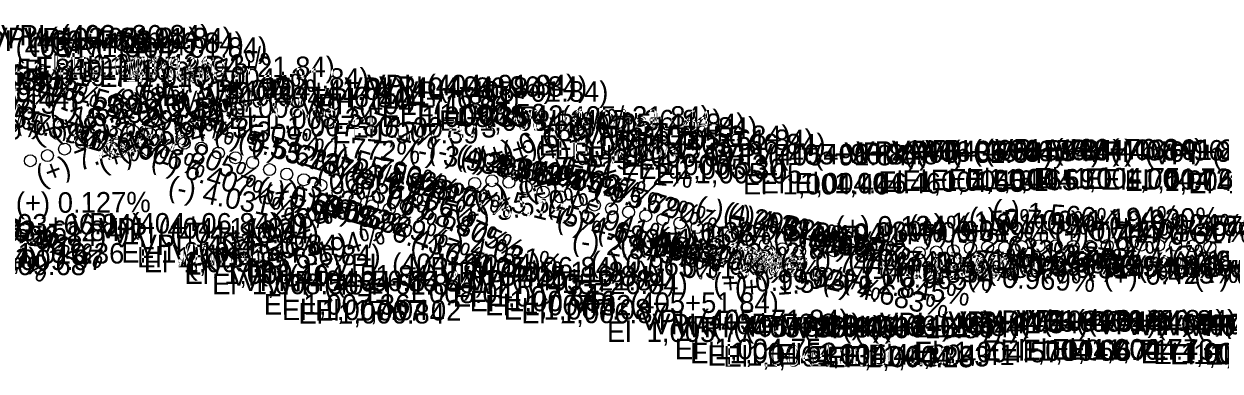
# Model space of a CAD drawing. Extents: x 16970812 to 16976737, y 12558429 to 12559451.
# Drawn here: x 16974747.9 to 16975097.7, y 12558926.1 to 12559027.7 of the extents above; entities that cross this region are included whole.
import ezdxf

# ---------------------------------------------------------------- set-up
doc = ezdxf.new("R2010")
doc.units = 0
doc.layers.add('RD_DDB_GradeTX', color=7, linetype='Continuous')
doc.layers.add('RD_DDB_PI', color=7, linetype='Continuous')

msp = doc.modelspace()

# ---------------------------------------------------------------- linework, layer by layer
at = {"layer": 'RD_DDB_PI'}
for centre in [(16974769.74, 12558994.82), (16974774.74, 12558995.62), (16974779.74, 12558996.42), (16974784.74, 12558995.59), (16974759.74, 12558991.1), (16974764.74, 12558993.02), (16974789.74, 12558994.21), (16974794.74, 12558992.81), (16974799.74, 12558991.37), (16974749.74, 12558987.7), (16974754.74, 12558989.18), (16974804.74, 12558989.95), (16974809.74, 12558988.55), (16974814.74, 12558987.17), (16974819.74, 12558985.09), (16974824.74, 12558983.76), (16974829.74, 12558982.11), (16974879.74, 12558981.07), (16974884.74, 12558981.84), (16974889.74, 12558981.39), (16974834.74, 12558980.5), (16974839.74, 12558978.34), (16974869.74, 12558977.97), (16974874.74, 12558979.51), (16974894.74, 12558979.95), (16974899.74, 12558978.51), (16974904.74, 12558977.12), (16974844.74, 12558976.13), (16974849.74, 12558974.53), (16974859.74, 12558974.41), (16974864.74, 12558976.27), (16974909.74, 12558975.92), (16974914.74, 12558974.71), (16974919.74, 12558973.64), (16974854.74, 12558973.53), (16974924.74, 12558972.66), (16974929.74, 12558971.58), (16974934.74, 12558970.51), (16974939.74, 12558969.43), (16974944.74, 12558968.14), (16974949.74, 12558966.98), (16974954.74, 12558965.82), (16974959.74, 12558964.56), (16974964.74, 12558963.08), (16975069.74, 12558963.07), (16974969.74, 12558961.91), (16974974.74, 12558961.19), (16974979.74, 12558960.95), (16974984.74, 12558961.32), (16974989.74, 12558961.61), (16974994.74, 12558961.53), (16974999.74, 12558961.63), (16975004.74, 12558960.97), (16975009.74, 12558960.73), (16975014.74, 12558960.98), (16975019.74, 12558961.36), (16975024.74, 12558962.07), (16975029.74, 12558962.37), (16975034.74, 12558962.19), (16975039.74, 12558962.54), (16975044.74, 12558962.77), (16975049.74, 12558962.8), (16975054.74, 12558962.62), (16975059.74, 12558962.64), (16975064.74, 12558962.85), (16975074.74, 12558963), (16975079.74, 12558962.95), (16975084.74, 12558962.92), (16975089.74, 12558962.74), (16975094.74, 12558962.35)]:
    msp.add_circle(centre, 1.75, dxfattribs=at)

# ---------------------------------------------------------------- texts
at = {"layer": 'RD_DDB_GradeTX'}
for s, rotation, p in [('(+) 7.173%', 19.7305, (16974783.44, 12559002.92)), ('(-) 5.532%', 344.5396, (16974726.19, 12559014.9)), ('(-) 5.613%', 344.3231, (16974733.31, 12559013.16)), ('(-) 3.309%', 350.6045, (16974719.65, 12559009.41)), ('(+) 7.308%', 20.0734, (16974751.55, 12558992.47)), ('(-) 5.522%', 344.5648, (16974751.23, 12559007.81)), ('(+) 6.308%', 17.5064, (16974756.79, 12558993.48)), ('(-) 8.647%', 336.6189, (16974780.84, 12559007.07)), ('(+) 3.220%', 9.1473, (16974787.26, 12559000.68)), ('(+) 3.199%', 9.0882, (16974794.6, 12559001.84)), ('(-) 8.306%', 337.4469, (16974755.17, 12559002.16)), ('(-) 5.329%', 345.0802, (16974761.22, 12559003.79)), ('(+) 4.640%', 13.0615, (16974762.91, 12558993.83)), ('(-) 6.437%', 342.1594, (16974773.06, 12559003.5)), ('(+) 7.654%', 20.9421, (16974776.09, 12558987.72)), ('(+) 7.705%', 21.07, (16974781.14, 12558989.7)), ('(-) 5.737%', 343.9957, (16974733.98, 12559000.87)), ('(-) 5.690%', 344.1187, (16974738.91, 12558999.32)), ('(-) 5.762%', 343.9296, (16974832.2, 12559001.09)), ('(+) 6.194%', 17.2079, (16974888.92, 12558987.04)), ('(+) 3.199%', 9.0882, (16974715.67, 12558989.21)), ('(-) 5.615%', 344.3167, (16974745.24, 12558997.31)), ('(+) 5.954%', 16.5775, (16974770.52, 12558984.49)), ('(-) 3.309%', 350.6045, (16974798.51, 12558996.36)), ('(+) 6.788%', 18.7474, (16974882.16, 12558985.35)), ('(+) 7.491%', 20.5323, (16974752.73, 12558980.26)), ('(-) 6.606%', 341.7206, (16974764.58, 12558994.15)), ('(-) 8.805%', 336.2393, (16974780.6, 12558994.54)), ('(-) 5.532%', 344.5396, (16974803.11, 12558993.63)), ('(-) 5.613%', 344.3231, (16974810.15, 12558991.6)), ('(+) 3.068%', 8.7226, (16974897.89, 12558986.89)), ('(-) 5.737%', 343.9957, (16974814, 12558990.41)), ('(-) 1.772%', 354.938, (16974826.26, 12558990.03)), ('(-) 5.790%', 343.854, (16974834.12, 12558988.13)), ('(-) 3.938%', 348.8596, (16974860.1, 12558988.45)), ('(-) 4.299%', 347.8682, (16974865.96, 12558988.36)), ('(+) 6.223%', 17.2824, (16974894.93, 12558976.37)), ('(-) 6.407%', 342.2362, (16974784.64, 12558985.94)), ('(-) 5.536%', 344.5286, (16974838.33, 12558986.17)), ('(-) 4.311%', 347.8348, (16974873.91, 12558986.69)), ('(-) 4.323%', 347.8021, (16974875.17, 12558986.45)), ('(+) 7.422%', 20.3594, (16974880.63, 12558972.56)), ('(-) 4.627%', 346.9751, (16974886.4, 12558984.71)), ('(-) 4.659%', 346.8864, (16974891.37, 12558983.66)), ('(+) 3.068%', 8.7226, (16974818.87, 12558974.77)), ('(-) 8.306%', 337.4469, (16974833.27, 12558982.72)), ('(-) 4.823%', 346.442, (16974843.06, 12558982.74)), ('(-) 6.606%', 341.7206, (16974844.06, 12558980.54)), ('(-) 4.810%', 346.4763, (16974850.19, 12558980.98)), ('(-) 5.027%', 345.8922, (16974896.4, 12558983.57)), ('(-) 1.772%', 354.938, (16974905.93, 12558982.97)), ('(-) 4.031%', 348.6043, (16974789.71, 12558977.45)), ('(-) 5.690%', 344.1187, (16974815.66, 12558977.49)), ('(-) 4.277%', 347.9279, (16974853.78, 12558978.55)), ('(-) 5.762%', 343.9296, (16974908.88, 12558979)), ('(-) 5.790%', 343.854, (16974914.11, 12558977.47)), ('(+) 6.223%', 17.2824, (16974815.21, 12558964.13)), ('(-) 5.615%', 344.3167, (16974822.08, 12558975.74)), ('(-) 5.522%', 344.5648, (16974824.97, 12558975.01)), ('(-) 8.647%', 336.6189, (16974853.86, 12558975.5)), ('(+) 3.550%', 10.0648, (16974874.49, 12558967.89)), ('(-) 5.145%', 345.5743, (16974880.06, 12558975.48)), ('(-) 11.243%', 330.6573, (16974716.68, 12558972.27)), ('(-) 7.074%', 340.5204, (16974725.32, 12558971.44)), ('(+) 0.127%', 0.3642, (16974745.51, 12558972.36)), ('(+) 6.788%', 18.7474, (16974806.67, 12558959.73)), ('(-) 5.329%', 345.0802, (16974835.27, 12558971.64)), ('(-) 8.805%', 336.2393, (16974858.23, 12558973.48)), ('(-) 5.941%', 343.4548, (16974900.61, 12558972.74)), ('(-) 4.299%', 347.8682, (16974944.06, 12558971.58)), ('(-) 4.311%', 347.8348, (16974952, 12558969.85)), ('(-) 4.323%', 347.8021, (16974953.25, 12558969.57)), ('(-) 1.566%', 355.5233, (16975030.94, 12558970.36)), ('(-) 7.041%', 340.6064, (16974731.62, 12558969.24)), ('(-) 6.962%', 340.807, (16974734.83, 12558968.18)), ('(+) 7.422%', 20.3594, (16974801.76, 12558956.1)), ('(-) 6.437%', 342.1594, (16974845.29, 12558967.65)), ('(-) 4.683%', 346.8212, (16974903.37, 12558968.2)), ('(-) 5.145%', 345.5743, (16974960.37, 12558967.22)), ('(+) 1.157%', 3.311, (16975007.01, 12558965.61)), ('(-) 0.115%', 359.6692, (16975021.94, 12558966.28)), ('(-) 0.700%', 357.9941, (16975024.18, 12558968.04)), ('(+) 1.194%', 3.4171, (16975047.06, 12558966.41)), ('(+) 0.930%', 2.6636, (16975058.4, 12558966.41)), ('(+) 0.124%', 0.3549, (16975065.25, 12558965.9)), ('(-) 0.557%', 358.4036, (16975073.91, 12558966.35)), ('(-) 0.303%', 359.1328, (16975088.19, 12558965.8)), ('(+) 6.194%', 17.2079, (16974816.27, 12558951.98)), ('(-) 5.536%', 344.5286, (16974915.25, 12558964.87)), ('(-) 4.823%', 346.442, (16974920.7, 12558964.02)), ('(+) 1.471%', 4.2067, (16974922.41, 12558959.74)), ('(+) 1.157%', 3.311, (16974927.15, 12558960.99)), ('(+) 0.384%', 1.1002, (16974933.51, 12558963.35)), ('(+) 1.194%', 3.4171, (16974967.21, 12558961.64)), ('(-) 4.659%', 346.8864, (16974969.15, 12558965.54)), ('(-) 5.027%', 345.8922, (16974973.84, 12558964.11)), ('(+) 1.417%', 4.0537, (16974977.4, 12558961.13)), ('(+) 0.930%', 2.6636, (16974978.49, 12558962.69)), ('(+) 0.124%', 0.3549, (16974985.26, 12558965.4)), ('(+) 0.904%', 2.589, (16975003.91, 12558963.1)), ('(-) 0.319%', 359.0866, (16975010.26, 12558964.28)), ('(+) 0.477%', 1.3674, (16975049.39, 12558963.12)), ('(-) 0.744%', 357.8701, (16975049.37, 12558964.64)), ('(-) 0.740%', 357.881, (16975069.25, 12558965.08)), ('(+) 0.617%', 1.766, (16975070.74, 12558962.68)), ('(+) 3.550%', 10.0648, (16974795.8, 12558953.92)), ('(-) 6.407%', 342.2362, (16974860.59, 12558961.61)), ('(-) 4.031%', 348.6043, (16974868.03, 12558961.67)), ('(-) 2.845%', 351.9036, (16974907.89, 12558961.61)), ('(-) 4.810%', 346.4763, (16974927.83, 12558962.31)), ('(-) 4.277%', 347.9279, (16974931.9, 12558961.84)), ('(-) 3.938%', 348.8596, (16974936.18, 12558961.23)), ('(-) 2.632%', 352.5034, (16974937.48, 12558960.74)), ('(+) 2.849%', 8.1075, (16974958.97, 12558955.74)), ('(-) 5.941%', 343.4548, (16974980.5, 12558961.52)), ('(-) 2.632%', 352.5034, (16975018.32, 12558962.21)), ('(-) 1.877%', 354.6387, (16975035.42, 12558958.88)), ('(+) 2.849%', 8.1075, (16975039.82, 12558955.13)), ('(-) 0.965%', 357.2376, (16974913.5, 12558955.14)), ('(-) 0.744%', 357.8701, (16974968.98, 12558955.63)), ('(-) 0.740%', 357.881, (16974988.86, 12558956.05)), ('(+) 1.471%', 4.2067, (16975003.06, 12558953.64)), ('(+) 1.543%', 4.4116, (16975035.73, 12558953.57)), ('(-) 0.983%', 357.1871, (16975038.2, 12558955.9)), ('(+) 1.417%', 4.0537, (16975058.04, 12558954.81)), ('(+) 0.832%', 2.3829, (16975078.56, 12558954.42)), ('(-) 1.411%', 355.9634, (16975083.33, 12558956.47)), ('(+) 0.904%', 2.589, (16975084.36, 12558954.73)), ('(-) 0.319%', 359.0866, (16974930.08, 12558953.56)), ('(-) 0.969%', 357.226, (16974943.73, 12558954.91)), ('(-) 4.627%', 346.9751, (16974961.51, 12558955.02)), ('(+) 0.085%', 0.2447, (16974993.66, 12558953.36)), ('(+) 0.832%', 2.3829, (16974998.64, 12558951.09)), ('(-) 0.303%', 359.1328, (16975008.02, 12558955.01)), ('(-) 0.209%', 359.401, (16975013.53, 12558954.64)), ('(+) 0.384%', 1.1002, (16975013.73, 12558952.89)), ('(+) 0.999%', 2.8602, (16975029.52, 12558952.7)), ('(-) 0.314%', 359.1012, (16975045.08, 12558953.57)), ('(-) 0.598%', 358.2878, (16975053.5, 12558954.5)), ('(-) 0.545%', 358.4399, (16975058.4, 12558954.2)), ('(+) 0.425%', 1.2186, (16975063.71, 12558951.09)), ('(+) 0.085%', 0.2447, (16975073.66, 12558953.7)), ('(-) 0.624%', 358.2125, (16975083.49, 12558954.07)), ('(-) 0.209%', 359.401, (16975093.52, 12558953.8)), ('(+) 0.999%', 2.8602, (16974949.62, 12558948.71)), ('(+) 1.543%', 4.4116, (16974955.98, 12558947.42)), ('(-) 4.683%', 346.8212, (16974981.13, 12558950)), ('(-) 2.845%', 351.9036, (16974987.05, 12558950.35)), ('(-) 0.965%', 357.2376, (16974993.4, 12558951.28)), ('(-) 0.969%', 357.226, (16975023.63, 12558951.04)), ('(+) 0.310%', 0.8881, (16975090.24, 12558951.08))]:
    msp.add_text(s, height=6, rotation=rotation, dxfattribs=at).set_placement(p)
at = {"layer": 'RD_DDB_PI'}
for s, p in [('VPI  (403+71.84)', (16974728.04, 12559018.02)), ('VPI  (403+76.84)', (16974731.5, 12559019.82)), ('VPI  (403+81.84)', (16974737.74, 12559020.62)), ('VPI  (403+86.84)', (16974741.21, 12559021.42)), ('VPI  (403+91.84)', (16974747.86, 12559020.59)), ('VPI  (403+96.84)', (16974751.33, 12559019.21)), ('VPI  (404+01.84)', (16974758.16, 12559017.81)), ('VPI  (403+51.84)', (16974707.63, 12559011.54)), ('El  1,011.10', (16974747.89, 12559011.32)), ('El  1,011.26', (16974751.12, 12559012.12)), ('El  1,011.42', (16974756.15, 12559012.92)), ('El  1,011.26', (16974761.12, 12559012.09)), ('VPI  (404+21.84)', (16974777.92, 12559012.17)), ('VPI  (403+41.84)', (16974697.86, 12559008.13)), ('VPI  (403+46.84)', (16974701.33, 12559009.96)), ('El  1,010.74', (16974740, 12559009.52)), ('El  1,010.98', (16974764.73, 12559010.71)), ('El  1,010.70', (16974769.88, 12559009.31)), ('VPI  (404+31.84)', (16974787.86, 12559008.76)), ('VPI  (404+41.84)', (16974798.27, 12559005.5)), ('VPI  (404+86.84)', (16974841.62, 12559006.07)), ('VPI  (404+91.84)', (16974848.27, 12559006.84)), ('VPI  (404+96.84)', (16974851.74, 12559006.39)), ('VPI  (405+01.84)', (16974857.92, 12559004.95)), ('El  1,009.13', (16974714.44, 12559001.46)), ('El  1,009.44', (16974718.28, 12559003.04)), ('El  1,009.57', (16974788.23, 12559003.67)), ('VPI  (404+46.84)', (16974801.74, 12559003.34)), ('VPI  (404+71.84)', (16974828.45, 12559001.27)), ('VPI  (404+76.84)', (16974831.92, 12559002.97)), ('El  1,008.76', (16974708.34, 12558999.63)), ('El  1,008.89', (16974798.05, 12559000.26)), ('El  1,008.24', (16974807.81, 12558997)), ('El  1,008.35', (16974852.55, 12558997.57)), ('El  1,008.50', (16974857.81, 12558998.34)), ('El  1,008.42', (16974862.84, 12558997.89)), ('VPI  (405+31.84)', (16974887.63, 12558997.66)), ('El  1,007.80', (16974813.23, 12558994.84)), ('El  1,007.73', (16974843.26, 12558994.47)), ('El  1,008.13', (16974869.32, 12558996.45)), ('VPI  (405+36.84)', (16974891.09, 12558996.58)), ('VPI  (405+41.84)', (16974898.04, 12558995.51)), ('VPI  (405+46.84)', (16974901.5, 12558994.43)), ('El  1,007.39', (16974838.05, 12558992.77)), ('VPI  (405+56.84)', (16974911.27, 12558991.98)), ('VPI  (405+61.84)', (16974918.04, 12558990.82)), ('El  1,006.67', (16974898.46, 12558989.16)), ('El  1,006.45', (16974903.08, 12558988.08)), ('El  1,006.24', (16974907.93, 12558987.01)), ('VPI  (405+66.84)', (16974921.5, 12558989.56)), ('VPI  (405+96.84)', (16974951.5, 12558986.61)), ('VPI  (406+06.84)', (16974961.62, 12558986.63)), ('VPI  (406+31.84)', (16974987.86, 12558987.07)), ('VPI  (406+36.84)', (16974991.33, 12558987.37)), ('VPI  (406+46.84)', (16975001.74, 12558987.54)), ('VPI  (406+51.84)', (16975008.04, 12558987.77)), ('VPI  (406+56.84)', (16975011.5, 12558987.8)), ('VPI  (406+76.84)', (16975031.92, 12558988.07)), ('VPI  (406+91.84)', (16975048.27, 12558987.92)), ('VPI  (406+96.84)', (16975051.74, 12558987.74)), ('VPI  (407+01.84)', (16975058.33, 12558987.35)), ('VPI  (407+21.84)', (16975078.1, 12558986.68)), ('El  1,006.02', (16974912.84, 12558985.93)), ('El  1,005.53', (16974922.43, 12558983.48)), ('VPI  (405+91.84)', (16974948.04, 12558986.32)), ('El  1,005.30', (16974927.52, 12558982.32)), ('El  1,005.05', (16974932.72, 12558981.06)), ('El  1,004.75', (16975043.26, 12558979.57)), ('El  1,004.40', (16974958.17, 12558977.82)), ('El  1,004.46', (16974963.28, 12558978.11)), ('El  1,004.46', (16974973.28, 12558978.13)), ('El  1,004.55', (16974997.84, 12558978.57)), ('El  1,004.61', (16975004.82, 12558978.87)), ('El  1,004.65', (16975013.08, 12558979.04)), ('El  1,004.69', (16975018.28, 12558979.27)), ('El  1,004.70', (16975023.34, 12558979.3)), ('El  1,004.72', (16975058.14, 12558979.42)), ('El  1,004.69', (16975063.28, 12558979.24)), ('El  1,004.61', (16975069.82, 12558978.85)), ('El  1,004.47', (16975088.46, 12558978.18)), ('VPI  (403+66.84)', (16974721.33, 12558966.1)), ('VPI  (404+06.84)', (16974761.62, 12558966.37)), ('VPI  (403+56.84)', (16974711.09, 12558962.7)), ('VPI  (403+61.84)', (16974717.86, 12558964.18)), ('VPI  (404+11.84)', (16974769.81, 12558964.95)), ('VPI  (404+16.84)', (16974773.27, 12558963.55)), ('VPI  (404+26.84)', (16974781.39, 12558960.09)), ('VPI  (403+36.84)', (16974690.91, 12558956.26)), ('El  1,009.97', (16974728.46, 12558955.68)), ('El  1,010.36', (16974734.41, 12558957.6)), ('El  1,010.41', (16974776.36, 12558957.87)), ('El  1,010.13', (16974780.97, 12558956.45)), ('El  1,009.85', (16974782.96, 12558955.05)), ('VPI  (404+36.84)', (16974791.33, 12558957.11)), ('El  1,009.68', (16974723.2, 12558954.2)), ('El  1,009.16', (16974794.82, 12558951.59)), ('VPI  (404+81.84)', (16974838.16, 12558954.51)), ('VPI  (405+06.84)', (16974861.39, 12558953.51)), ('VPI  (405+11.84)', (16974869.57, 12558952.12)), ('El  1,008.56', (16974802.93, 12558948.61)), ('VPI  (404+51.84)', (16974808.04, 12558951.13)), ('VPI  (404+56.84)', (16974811.5, 12558949.53)), ('VPI  (404+61.84)', (16974818.27, 12558948.53)), ('VPI  (404+66.84)', (16974821.74, 12558949.41)), ('VPI  (405+16.84)', (16974873.04, 12558950.92)), ('VPI  (405+21.84)', (16974877.68, 12558949.71)), ('VPI  (405+26.84)', (16974881.15, 12558948.64)), ('El  1,008.04', (16974848.05, 12558946.01)), ('El  1,007.84', (16974873.34, 12558945.01)), ('El  1,007.36', (16974818.05, 12558942.63)), ('El  1,007.04', (16974823.34, 12558941.03)), ('El  1,007.56', (16974878.23, 12558943.62)), ('El  1,007.32', (16974882.72, 12558942.42)), ('El  1,007.08', (16974888.26, 12558941.21)), ('VPI  (405+51.84)', (16974907.8, 12558943.14)), ('El  1,006.84', (16974828.17, 12558940.03)), ('El  1,007.02', (16974833.02, 12558940.91)), ('El  1,006.87', (16974893.34, 12558940.14)), ('VPI  (405+71.84)', (16974928.22, 12558938.08)), ('VPI  (406+61.84)', (16975018.27, 12558937.62)), ('VPI  (406+66.84)', (16975021.74, 12558937.64)), ('VPI  (406+71.84)', (16975028.45, 12558937.85)), ('VPI  (406+81.84)', (16975038.16, 12558938)), ('VPI  (406+86.84)', (16975041.62, 12558937.95)), ('El  1,005.77', (16974918.4, 12558934.64)), ('VPI  (405+76.84)', (16974931.68, 12558936.91)), ('VPI  (405+81.84)', (16974937.92, 12558936.19)), ('VPI  (405+86.84)', (16974941.39, 12558935.95)), ('VPI  (406+01.84)', (16974958.16, 12558936.53)), ('VPI  (406+11.84)', (16974969.81, 12558935.97)), ('VPI  (406+16.84)', (16974973.27, 12558935.73)), ('VPI  (406+21.84)', (16974977.92, 12558935.98)), ('VPI  (406+26.84)', (16974981.39, 12558936.36)), ('VPI  (406+41.84)', (16974998.27, 12558937.19)), ('VPI  (407+06.84)', (16975061.8, 12558936.88)), ('VPI  (407+11.84)', (16975069.99, 12558936.64)), ('VPI  (407+16.84)', (16975073.45, 12558936.56)), ('VPI  (407+26.84)', (16975081.56, 12558936.53)), ('VPI  (407+31.84)', (16975088.04, 12558936.39)), ('VPI  (407+36.84)', (16975091.5, 12558936.5)), ('El  1,004.75', (16974938.26, 12558929.58)), ('El  1,004.52', (16974942.72, 12558928.41)), ('El  1,004.38', (16974947.78, 12558927.69)), ('El  1,004.33', (16974952.49, 12558927.45)), ('El  1,004.44', (16974968.28, 12558928.03)), ('El  1,004.33', (16974977.49, 12558927.47)), ('El  1,004.28', (16974982.84, 12558927.23)), ('El  1,004.33', (16974987.49, 12558927.48)), ('El  1,004.41', (16974994.82, 12558927.86)), ('El  1,004.57', (16975008.23, 12558928.69)), ('El  1,004.66', (16975028.28, 12558929.12)), ('El  1,004.67', (16975033.46, 12558929.14)), ('El  1,004.71', (16975040, 12558929.35)), ('El  1,004.74', (16975048.46, 12558929.5)), ('El  1,004.73', (16975053.08, 12558929.45)), ('El  1,004.51', (16975074.58, 12558928.38)), ('El  1,004.46', (16975078.28, 12558928.14)), ('El  1,004.45', (16975083.08, 12558928.06)), ('El  1,004.44', (16975093.28, 12558928.03))]:
    msp.add_text(s, height=6, dxfattribs=at).set_placement(p)

doc.saveas('drawing.dxf')
